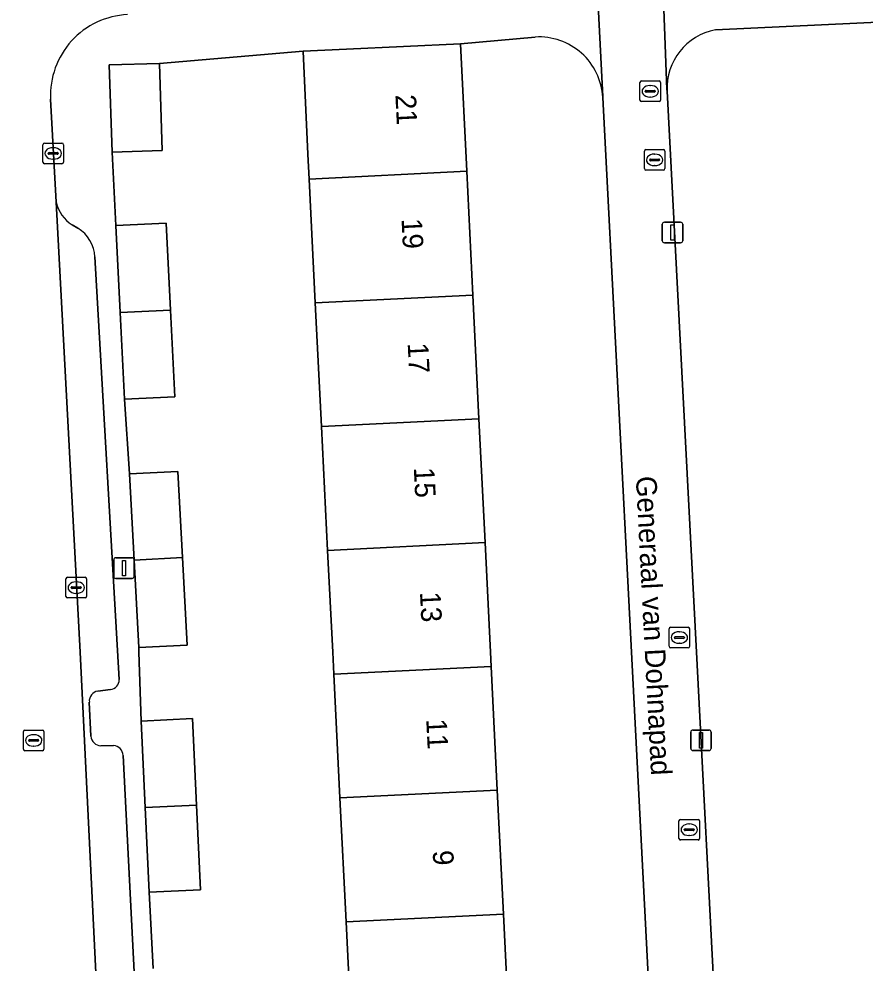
# Model space of a CAD drawing. Extents: x 161084 to 161928, y 385354 to 386522.
# Drawn here: x 161466.13 to 161507.27, y 385484.89 to 385530.8 of the extents above; entities that cross this region are included whole.
import ezdxf

# ---------------------------------------------------------------- set-up
doc = ezdxf.new("R2010")
doc.units = 0
for name, color, linetype in [('IMGEO_Erf', 7, 'Continuous'), ('IMGEO_Kolk', 7, 'Continuous'), ('IMGEO_Lichtmast', 7, 'Continuous'), ('IMGEO_Muur', 7, 'Continuous'), ('IMGEO_Openbare_ruimte_label', 7, 'Continuous'), ('IMGEO_Pand', 7, 'Continuous'), ('IMGEO_Pand_nummerreeks', 7, 'Continuous'), ('IMGEO_Parkeervlak_open', 7, 'Continuous'), ('IMGEO_Rijbaan_lokaal_open', 7, 'Continuous'), ('IMGEO_Rioolput', 7, 'Continuous'), ('IMGEO_Voetpad_open', 7, 'Continuous')]:
    doc.layers.add(name, color=color, linetype=linetype)

msp = doc.modelspace()

# ---------------------------------------------------------------- linework, layer by layer
at = {"layer": 'IMGEO_Erf'}
for points in [[(161508.582, 385530.67), (161500, 385530.265)], [(161491.237, 385529.914), (161487.598, 385529.579), (161487.904, 385523.388), (161488.201, 385517.369), (161488.498, 385511.35), (161488.796, 385505.332), (161489.059, 385500), (161489.093, 385499.313), (161489.39, 385493.295), (161489.687, 385487.276), (161489.985, 385481.257), (161490.282, 385475.239), (161490.579, 385469.22), (161490.885, 385463.029), (161485.288, 385462.74), (161485.591, 385456.852), (161485.631, 385456.187), (161495.554, 385456.711)], [(161482.344, 385480.88), (161482.044, 385486.899), (161481.745, 385492.918), (161481.445, 385498.936), (161481.392, 385500), (161481.145, 385504.954), (161480.846, 385510.972), (161480.546, 385516.991), (161480.247, 385523.01), (161480.186, 385524.228), (161479.95, 385529.222), (161472.967, 385528.635), (161473.104, 385524.399), (161470.663, 385524.321), (161470.855, 385520.745), (161473.294, 385520.866), (161473.505, 385516.643), (161473.715, 385512.428), (161471.276, 385512.307), (161471.508, 385508.673), (161473.867, 385508.799), (161474.09, 385504.605), (161474.316, 385500.355), (161471.958, 385500.23), (161471.966, 385500), (161472.079, 385496.658), (161474.573, 385496.777), (161474.773, 385492.574), (161474.968, 385488.456), (161472.473, 385488.338), (161472.655, 385484.634)], [(161497.649, 385527.286), (161499.071, 385500), (161500, 385482.173), (161501.185, 385459.434)], [(161498.014, 385459.443), (161495.914, 385500), (161494.517, 385526.983)]]:
    msp.add_lwpolyline(points, dxfattribs=at)
for centre, radius, start, end in [((161500.523, 385527.435), 2.878, 100.4719, 182.9677), ((161491.421, 385526.82), 3.1, 3.0225, 93.4098)]:
    msp.add_arc(centre, radius, start, end, dxfattribs=at)
at = {"layer": 'IMGEO_Kolk'}
for p, q in [((161496.402, 385527.778), (161497.254, 385527.778)), ((161496.327, 385526.852), (161496.327, 385527.704)), ((161496.586, 385527.272), (161496.586, 385527.284)), ((161496.629, 385527.321), (161497.027, 385527.321)), ((161496.815, 385527.558), (161496.84, 385527.558)), ((161497.07, 385527.284), (161497.07, 385527.272)), ((161497.328, 385527.704), (161497.328, 385526.852)), ((161497.024, 385527.235), (161496.626, 385527.235)), ((161496.838, 385526.998), (161496.813, 385526.998)), ((161497.254, 385526.778), (161496.402, 385526.778)), ((161467.302, 385523.83), (161467.302, 385524.682)), ((161467.377, 385524.756), (161468.229, 385524.756)), ((161467.79, 385524.536), (161467.815, 385524.536)), ((161468.303, 385524.682), (161468.303, 385523.83)), ((161467.561, 385524.25), (161467.561, 385524.262)), ((161467.999, 385524.213), (161467.601, 385524.213)), ((161467.604, 385524.299), (161468.002, 385524.299)), ((161468.045, 385524.262), (161468.045, 385524.25)), ((161496.541, 385523.516), (161496.541, 385524.368)), ((161496.616, 385524.442), (161497.468, 385524.442)), ((161497.029, 385524.222), (161497.054, 385524.222)), ((161497.542, 385524.368), (161497.542, 385523.516)), ((161468.229, 385523.756), (161467.377, 385523.756)), ((161467.813, 385523.976), (161467.788, 385523.976)), ((161496.8, 385523.936), (161496.8, 385523.948)), ((161497.238, 385523.899), (161496.84, 385523.899)), ((161496.843, 385523.985), (161497.241, 385523.985)), ((161497.052, 385523.662), (161497.027, 385523.662)), ((161497.284, 385523.948), (161497.284, 385523.936)), ((161497.468, 385523.442), (161496.616, 385523.442)), ((161468.424, 385502.721), (161468.424, 385503.573)), ((161468.499, 385503.647), (161469.351, 385503.647)), ((161468.912, 385503.427), (161468.937, 385503.427)), ((161469.425, 385503.573), (161469.425, 385502.721)), ((161468.683, 385503.141), (161468.683, 385503.153)), ((161469.121, 385503.104), (161468.723, 385503.104)), ((161468.726, 385503.19), (161469.124, 385503.19)), ((161469.167, 385503.153), (161469.167, 385503.141)), ((161469.351, 385502.647), (161468.499, 385502.647)), ((161468.935, 385502.867), (161468.91, 385502.867)), ((161497.743, 385500.293), (161497.743, 385501.145)), ((161497.818, 385501.219), (161498.67, 385501.219)), ((161498.744, 385501.145), (161498.744, 385500.293)), ((161498.002, 385500.713), (161498.002, 385500.725)), ((161498.44, 385500.676), (161498.042, 385500.676)), ((161498.045, 385500.762), (161498.443, 385500.762)), ((161498.231, 385500.999), (161498.256, 385500.999)), ((161498.486, 385500.725), (161498.486, 385500.713)), ((161498.67, 385500.219), (161497.818, 385500.219)), ((161498.254, 385500.439), (161498.229, 385500.439))]:
    msp.add_line(p, q, dxfattribs=at)
for points in [[(161496.402, 385527.778), (161497.254, 385527.778)], [(161496.327, 385526.852), (161496.327, 385527.704)], [(161497.328, 385527.704), (161497.328, 385526.852)], [(161497.254, 385526.778), (161496.402, 385526.778)], [(161467.302, 385523.83), (161467.302, 385524.682)], [(161467.377, 385524.756), (161468.229, 385524.756)], [(161468.303, 385524.682), (161468.303, 385523.83)], [(161496.541, 385523.516), (161496.541, 385524.368)], [(161496.616, 385524.442), (161497.468, 385524.442)], [(161497.542, 385524.368), (161497.542, 385523.516)], [(161468.229, 385523.756), (161467.377, 385523.756)], [(161497.468, 385523.442), (161496.616, 385523.442)], [(161468.424, 385502.721), (161468.424, 385503.573)], [(161468.499, 385503.647), (161469.351, 385503.647)], [(161469.425, 385503.573), (161469.425, 385502.721)], [(161469.351, 385502.647), (161468.499, 385502.647)], [(161497.743, 385500.293), (161497.743, 385501.145)], [(161497.818, 385501.219), (161498.67, 385501.219)], [(161498.744, 385501.145), (161498.744, 385500.293)], [(161498.67, 385500.219), (161497.818, 385500.219)]]:
    msp.add_lwpolyline(points, dxfattribs=at)
for centre, radius, start, end in [((161496.404, 385527.702), 0.0765, 91.552, 178.448), ((161496.404, 385527.702), 0.0765, 91.552, 178.448), ((161497.252, 385527.702), 0.0765, 1.552, 88.448), ((161497.252, 385527.702), 0.0765, 1.552, 88.448), ((161496.626, 385527.281), 0.0403, 85.8775, 175.7526), ((161497.031, 385527.283), 0.0386, 1.7309, 96.639), ((161496.404, 385526.854), 0.0765, 181.552, 268.448), ((161496.404, 385526.854), 0.0765, 181.552, 268.448), ((161496.623, 385527.271), 0.0366, 178.938, 274.7102), ((161497.027, 385527.278), 0.043, 264.8664, 352.4533), ((161497.252, 385526.854), 0.0765, 271.552, 358.448), ((161497.252, 385526.854), 0.0765, 271.552, 358.448), ((161467.379, 385524.68), 0.0765, 91.552, 178.448), ((161467.379, 385524.68), 0.0765, 91.552, 178.448), ((161468.227, 385524.68), 0.0765, 1.552, 88.448), ((161468.227, 385524.68), 0.0765, 1.552, 88.448), ((161467.601, 385524.259), 0.0403, 85.8775, 175.7526), ((161467.598, 385524.249), 0.0366, 178.938, 274.7102), ((161468.002, 385524.256), 0.043, 264.8664, 352.4533), ((161468.006, 385524.261), 0.0386, 1.7309, 96.639), ((161496.618, 385524.366), 0.0765, 91.552, 178.448), ((161496.618, 385524.366), 0.0765, 91.552, 178.448), ((161497.466, 385524.366), 0.0765, 1.552, 88.448), ((161497.466, 385524.366), 0.0765, 1.552, 88.448), ((161467.379, 385523.832), 0.0765, 181.552, 268.448), ((161467.379, 385523.832), 0.0765, 181.552, 268.448), ((161468.227, 385523.832), 0.0765, 271.552, 358.448), ((161468.227, 385523.832), 0.0765, 271.552, 358.448), ((161496.84, 385523.945), 0.0403, 85.8775, 175.7526), ((161496.837, 385523.935), 0.0366, 178.938, 274.7102), ((161497.241, 385523.942), 0.043, 264.8664, 352.4533), ((161497.245, 385523.947), 0.0386, 1.7309, 96.639), ((161496.618, 385523.518), 0.0765, 181.552, 268.448), ((161496.618, 385523.518), 0.0765, 181.552, 268.448), ((161497.466, 385523.518), 0.0765, 271.552, 358.448), ((161497.466, 385523.518), 0.0765, 271.552, 358.448), ((161468.501, 385503.571), 0.0765, 91.552, 178.448), ((161468.501, 385503.571), 0.0765, 91.552, 178.448), ((161469.349, 385503.571), 0.0765, 1.552, 88.448), ((161469.349, 385503.571), 0.0765, 1.552, 88.448), ((161468.723, 385503.15), 0.0403, 85.8775, 175.7526), ((161468.72, 385503.14), 0.0366, 178.938, 274.7102), ((161469.124, 385503.147), 0.043, 264.8664, 352.4533), ((161469.128, 385503.152), 0.0386, 1.7309, 96.639), ((161468.501, 385502.723), 0.0765, 181.552, 268.448), ((161468.501, 385502.723), 0.0765, 181.552, 268.448), ((161469.349, 385502.723), 0.0765, 271.552, 358.448), ((161469.349, 385502.723), 0.0765, 271.552, 358.448), ((161497.82, 385501.143), 0.0765, 91.552, 178.448), ((161497.82, 385501.143), 0.0765, 91.552, 178.448), ((161498.668, 385501.143), 0.0765, 1.552, 88.448), ((161498.668, 385501.143), 0.0765, 1.552, 88.448), ((161498.042, 385500.722), 0.0403, 85.8775, 175.7526), ((161498.039, 385500.712), 0.0366, 178.938, 274.7102), ((161498.443, 385500.719), 0.043, 264.8664, 352.4533), ((161498.447, 385500.724), 0.0386, 1.7309, 96.639), ((161497.82, 385500.295), 0.0765, 181.552, 268.448), ((161497.82, 385500.295), 0.0765, 181.552, 268.448), ((161498.668, 385500.295), 0.0765, 271.552, 358.448), ((161498.668, 385500.295), 0.0765, 271.552, 358.448)]:
    msp.add_arc(centre, radius, start, end, dxfattribs=at)
for centre, major_axis, ratio, start_param, end_param in [((161496.814, 385527.278), (-0.387, 0.002), 0.722429, 4.712389, 7.853982), ((161496.839, 385527.278), (-0.39, 0.002), 0.717154, 1.570796, 4.712389), ((161467.789, 385524.256), (-0.387, 0.002), 0.722429, 4.712389, 7.853982), ((161467.814, 385524.256), (-0.39, 0.002), 0.717154, 1.570796, 4.712389), ((161497.028, 385523.942), (-0.387, 0.002), 0.722429, 4.712389, 7.853982), ((161497.053, 385523.942), (-0.39, 0.002), 0.717154, 1.570796, 4.712389), ((161468.911, 385503.147), (-0.387, 0.002), 0.722429, 4.712389, 7.853982), ((161468.936, 385503.147), (-0.39, 0.002), 0.717154, 1.570796, 4.712389), ((161498.23, 385500.719), (-0.387, 0.002), 0.722429, 4.712389, 7.853982), ((161498.255, 385500.719), (-0.39, 0.002), 0.717154, 1.570796, 4.712389)]:
    msp.add_ellipse(centre, major_axis=major_axis, ratio=ratio, start_param=start_param, end_param=end_param, dxfattribs=at)
at = {"layer": 'IMGEO_Lichtmast'}
for p, q in [((161497.514, 385520.91), (161498.304, 385520.91)), ((161498.304, 385520.91), (161497.514, 385520.91)), ((161497.414, 385520.01), (161497.414, 385520.81)), ((161497.414, 385520.81), (161497.414, 385520.01)), ((161498.404, 385520.81), (161498.404, 385520.01)), ((161498.404, 385520.01), (161498.404, 385520.81)), ((161498.304, 385519.91), (161497.514, 385519.91)), ((161497.514, 385519.91), (161498.304, 385519.91)), ((161470.744, 385503.695), (161470.744, 385504.495)), ((161470.744, 385504.495), (161470.744, 385503.695)), ((161470.844, 385504.595), (161471.634, 385504.595)), ((161471.634, 385504.595), (161470.844, 385504.595)), ((161471.734, 385504.495), (161471.734, 385503.695)), ((161471.734, 385503.695), (161471.734, 385504.495)), ((161471.634, 385503.595), (161470.844, 385503.595)), ((161470.844, 385503.595), (161471.634, 385503.595)), ((161498.798, 385495.323), (161498.798, 385496.123)), ((161498.798, 385496.123), (161498.798, 385495.323)), ((161498.898, 385496.223), (161499.688, 385496.223)), ((161499.688, 385496.223), (161498.898, 385496.223)), ((161499.788, 385496.123), (161499.788, 385495.323)), ((161499.788, 385495.323), (161499.788, 385496.123)), ((161499.688, 385495.223), (161498.898, 385495.223)), ((161498.898, 385495.223), (161499.688, 385495.223))]:
    msp.add_line(p, q, dxfattribs=at)
for points in [[(161497.834, 385520.785), (161497.984, 385520.785), (161497.984, 385520.035), (161497.834, 385520.035), (161497.834, 385520.785)], [(161471.164, 385504.47), (161471.314, 385504.47), (161471.314, 385503.72), (161471.164, 385503.72), (161471.164, 385504.47)], [(161499.218, 385496.098), (161499.368, 385496.098), (161499.368, 385495.348), (161499.218, 385495.348), (161499.218, 385496.098)]]:
    msp.add_lwpolyline(points, dxfattribs=at)
for centre, start, end in [((161497.514, 385520.81), 90, 180), ((161497.514, 385520.81), 90, 180), ((161498.304, 385520.81), 0, 90), ((161498.304, 385520.81), 360, 90), ((161497.514, 385520.01), 180, 270), ((161497.514, 385520.01), 180, 270), ((161498.304, 385520.01), 270, 0), ((161498.304, 385520.01), 270, 0), ((161470.844, 385504.495), 90, 180), ((161470.844, 385504.495), 90, 180), ((161471.634, 385504.495), 0, 90), ((161471.634, 385504.495), 360, 90), ((161470.844, 385503.695), 180, 270), ((161470.844, 385503.695), 180, 270), ((161471.634, 385503.695), 270, 0), ((161471.634, 385503.695), 270, 0), ((161498.898, 385496.123), 90, 180), ((161498.898, 385496.123), 90, 180), ((161499.688, 385496.123), 0, 90), ((161499.688, 385496.123), 360, 90), ((161498.898, 385495.323), 180, 270), ((161498.898, 385495.323), 180, 270), ((161499.688, 385495.323), 270, 0), ((161499.688, 385495.323), 270, 0)]:
    msp.add_arc(centre, 0.1, start, end, dxfattribs=at)
at = {"layer": 'IMGEO_Muur'}
msp.add_lwpolyline([(161472.967, 385528.635), (161479.95, 385529.222)], dxfattribs=at)
at = {"layer": 'IMGEO_Pand'}
for points in [[(161479.95, 385529.222), (161480.186, 385524.228), (161480.247, 385523.01), (161487.904, 385523.388), (161487.598, 385529.579), (161482.064, 385529.321)], [(161470.526, 385528.556), (161470.663, 385524.321), (161473.104, 385524.399), (161472.967, 385528.635)], [(161488.201, 385517.369), (161487.904, 385523.388), (161480.247, 385523.01), (161480.546, 385516.991)], [(161471.066, 385516.523), (161473.505, 385516.643), (161473.294, 385520.866), (161470.855, 385520.745)], [(161488.498, 385511.35), (161488.201, 385517.369), (161480.546, 385516.991), (161480.846, 385510.972)], [(161471.276, 385512.307), (161473.715, 385512.428), (161473.505, 385516.643), (161471.066, 385516.523)], [(161480.846, 385510.972), (161481.145, 385504.954), (161488.796, 385505.332), (161488.498, 385511.35)], [(161471.731, 385504.489), (161474.09, 385504.605), (161473.867, 385508.799), (161471.508, 385508.673)], [(161489.093, 385499.313), (161489.059, 385500), (161488.796, 385505.332), (161481.145, 385504.954), (161481.392, 385500), (161481.445, 385498.936)], [(161471.958, 385500.23), (161474.316, 385500.355), (161474.09, 385504.605), (161471.731, 385504.489)], [(161489.39, 385493.295), (161489.093, 385499.313), (161481.445, 385498.936), (161481.745, 385492.918)], [(161472.278, 385492.451), (161474.773, 385492.574), (161474.573, 385496.777), (161472.079, 385496.658)], [(161489.687, 385487.276), (161489.39, 385493.295), (161481.745, 385492.918), (161482.044, 385486.899)], [(161472.473, 385488.338), (161474.968, 385488.456), (161474.773, 385492.574), (161472.278, 385492.451)], [(161482.044, 385486.899), (161482.344, 385480.88), (161489.985, 385481.257), (161489.687, 385487.276)]]:
    msp.add_lwpolyline(points, close=True, dxfattribs=at)
at = {"layer": 'IMGEO_Parkeervlak_open'}
for points in [[(161467.943, 385521.882), (161469.115, 385500), (161470.894, 385463.528)], [(161469.001, 385520.621), (161468.729, 385520.789)], [(161471.014, 385498.683), (161469.83, 385519.223)], [(161469.975, 385498.113), (161470.583, 385498.186)], [(161469.628, 385495.917), (161469.559, 385497.583)], [(161470.738, 385495.474), (161470.117, 385495.46)], [(161472.612, 385467.241), (161471.207, 385494.99)]]:
    msp.add_lwpolyline(points, dxfattribs=at)
for centre, radius, start, end in [((161469.651, 385522.281), 1.754, 193.1503, 238.2912), ((161468.078, 385519.129), 1.755, 3.0765, 58.2585), ((161470.526, 385498.67), 0.488, 276.6594, 1.4767), ((161470.042, 385497.632), 0.485, 97.8936, 185.8493), ((161470.135, 385495.969), 0.51, 185.9049, 267.9699), ((161470.686, 385494.955), 0.522, 3.8724, 84.3241)]:
    msp.add_arc(centre, radius, start, end, dxfattribs=at)
at = {"layer": 'IMGEO_Rijbaan_lokaal_open'}
msp.add_lwpolyline([(161462.601, 385526.611), (161462.868, 385521.205), (161463.964, 385500), (161465.916, 385462.228), (161466.247, 385455.821), (161466.286, 385455.063), (161468.791, 385455.186), (161471.295, 385455.308), (161471.256, 385456.104), (161470.894, 385463.528), (161469.115, 385500), (161467.943, 385521.882), (161467.675, 385526.897)], dxfattribs=at)
msp.add_arc((161471.593, 385527.085), 3.922, 92.6241, 182.748, dxfattribs=at)
at = {"layer": 'IMGEO_Rioolput'}
for p, q in [((161466.353, 385495.291), (161466.353, 385496.143)), ((161466.428, 385496.217), (161467.28, 385496.217)), ((161467.354, 385496.143), (161467.354, 385495.291)), ((161466.612, 385495.711), (161466.612, 385495.723)), ((161467.05, 385495.674), (161466.652, 385495.674)), ((161466.655, 385495.76), (161467.053, 385495.76)), ((161466.841, 385495.997), (161466.866, 385495.997)), ((161467.096, 385495.723), (161467.096, 385495.711)), ((161467.28, 385495.217), (161466.428, 385495.217)), ((161466.864, 385495.437), (161466.839, 385495.437)), ((161498.223, 385490.95), (161498.223, 385491.802)), ((161498.298, 385491.876), (161499.15, 385491.876)), ((161498.711, 385491.656), (161498.736, 385491.656)), ((161499.224, 385491.802), (161499.224, 385490.95)), ((161498.482, 385491.37), (161498.482, 385491.382)), ((161498.92, 385491.333), (161498.522, 385491.333)), ((161498.525, 385491.419), (161498.923, 385491.419)), ((161498.734, 385491.096), (161498.709, 385491.096)), ((161498.966, 385491.382), (161498.966, 385491.37)), ((161499.15, 385490.876), (161498.298, 385490.876))]:
    msp.add_line(p, q, dxfattribs=at)
for points in [[(161466.353, 385495.291), (161466.353, 385496.143)], [(161466.428, 385496.217), (161467.28, 385496.217)], [(161467.354, 385496.143), (161467.354, 385495.291)], [(161467.28, 385495.217), (161466.428, 385495.217)], [(161498.223, 385490.95), (161498.223, 385491.802)], [(161498.298, 385491.876), (161499.15, 385491.876)], [(161499.224, 385491.802), (161499.224, 385490.95)], [(161499.15, 385490.876), (161498.298, 385490.876)]]:
    msp.add_lwpolyline(points, dxfattribs=at)
for centre, radius, start, end in [((161466.43, 385496.141), 0.0765, 91.552, 178.448), ((161466.43, 385496.141), 0.0765, 91.552, 178.448), ((161467.278, 385496.141), 0.0765, 1.552, 88.448), ((161467.278, 385496.141), 0.0765, 1.552, 88.448), ((161466.652, 385495.72), 0.0403, 85.8775, 175.7526), ((161466.649, 385495.71), 0.0366, 178.938, 274.7102), ((161467.053, 385495.717), 0.043, 264.8664, 352.4533), ((161467.057, 385495.722), 0.0386, 1.7309, 96.639), ((161466.43, 385495.293), 0.0765, 181.552, 268.448), ((161466.43, 385495.293), 0.0765, 181.552, 268.448), ((161467.278, 385495.293), 0.0765, 271.552, 358.448), ((161467.278, 385495.293), 0.0765, 271.552, 358.448), ((161498.3, 385491.8), 0.0765, 91.552, 178.448), ((161498.3, 385491.8), 0.0765, 91.552, 178.448), ((161499.148, 385491.8), 0.0765, 1.552, 88.448), ((161499.148, 385491.8), 0.0765, 1.552, 88.448), ((161498.522, 385491.379), 0.0403, 85.8775, 175.7526), ((161498.519, 385491.369), 0.0366, 178.938, 274.7102), ((161498.923, 385491.376), 0.043, 264.8664, 352.4533), ((161498.927, 385491.381), 0.0386, 1.7309, 96.639), ((161498.3, 385490.952), 0.0765, 181.552, 268.448), ((161498.3, 385490.952), 0.0765, 181.552, 268.448), ((161499.148, 385490.952), 0.0765, 271.552, 358.448), ((161499.148, 385490.952), 0.0765, 271.552, 358.448)]:
    msp.add_arc(centre, radius, start, end, dxfattribs=at)
for centre, major_axis, ratio, start_param, end_param in [((161466.84, 385495.717), (-0.387, 0.002), 0.722429, 4.712389, 7.853982), ((161466.865, 385495.717), (-0.39, 0.002), 0.717154, 1.570796, 4.712389), ((161498.71, 385491.376), (-0.387, 0.002), 0.722429, 4.712389, 7.853982), ((161498.735, 385491.376), (-0.39, 0.002), 0.717154, 1.570796, 4.712389)]:
    msp.add_ellipse(centre, major_axis=major_axis, ratio=ratio, start_param=start_param, end_param=end_param, dxfattribs=at)
at = {"layer": 'IMGEO_Voetpad_open'}
for points in [[(161497.649, 385527.286), (161497.637, 385527.368), (161497.335, 385535.189), (161497.337, 385535.223), (161495.54, 385568.678)], [(161492.377, 385568.533), (161494.119, 385534.961), (161494.52, 385527.023), (161494.517, 385526.983), (161495.914, 385500), (161498.014, 385459.443)], [(161497.337, 385535.223), (161497.335, 385535.189), (161497.637, 385527.368), (161497.649, 385527.286)], [(161494.517, 385526.983), (161494.52, 385527.023), (161494.119, 385534.961)], [(161500, 385530.265), (161508.582, 385530.67)], [(161472.655, 385484.634), (161472.473, 385488.338), (161472.278, 385492.451), (161472.079, 385496.658), (161471.966, 385500), (161471.958, 385500.23), (161471.731, 385504.489), (161471.508, 385508.673), (161471.276, 385512.307), (161471.066, 385516.523), (161470.855, 385520.745), (161470.663, 385524.321), (161470.526, 385528.556), (161472.967, 385528.635), (161479.95, 385529.222), (161482.064, 385529.321), (161487.598, 385529.579), (161491.237, 385529.914)], [(161501.185, 385459.434), (161500, 385482.173), (161499.071, 385500), (161497.649, 385527.286)], [(161467.675, 385526.897), (161467.943, 385521.882)], [(161468.729, 385520.789), (161469.001, 385520.621)], [(161469.83, 385519.223), (161471.014, 385498.683)], [(161470.583, 385498.186), (161469.975, 385498.113)], [(161469.559, 385497.583), (161469.628, 385495.917)], [(161470.117, 385495.46), (161470.738, 385495.474)], [(161471.207, 385494.99), (161472.612, 385467.241)]]:
    msp.add_lwpolyline(points, dxfattribs=at)
for centre, radius, start, end in [((161471.593, 385527.085), 3.922, 92.6241, 182.748), ((161500.523, 385527.435), 2.878, 100.4719, 182.9677), ((161491.421, 385526.82), 3.1, 3.0225, 93.4098), ((161469.651, 385522.281), 1.754, 193.1503, 238.2912), ((161468.078, 385519.129), 1.755, 3.0765, 58.2585), ((161470.526, 385498.67), 0.488, 276.6594, 1.4767), ((161470.042, 385497.632), 0.485, 97.8936, 185.8493), ((161470.135, 385495.969), 0.51, 185.9049, 267.9699), ((161470.686, 385494.955), 0.522, 3.8724, 84.3241)]:
    msp.add_arc(centre, radius, start, end, dxfattribs=at)

# ---------------------------------------------------------------- texts
at = {"layer": 'IMGEO_Openbare_ruimte_label'}
msp.add_text('Generaal van Dohnapad', height=1, rotation=272.9225, dxfattribs=at).set_placement((161496.128, 385508.547))
at = {"layer": 'IMGEO_Pand_nummerreeks'}
for s, rotation, p in [('21', 272.8276, (161484.437, 385527.105)), ('19', 272.8276, (161484.735, 385521.077)), ('17', 272.8276, (161485.034, 385515.027)), ('15', 272.8276, (161485.332, 385508.977)), ('13', 272.8276, (161485.631, 385502.927)), ('11', 272.8275, (161485.936, 385496.748)), ('9', 272.8275, (161486.251, 385490.355))]:
    msp.add_text(s, height=1, rotation=rotation, dxfattribs=at).set_placement(p)

doc.saveas('drawing.dxf')
